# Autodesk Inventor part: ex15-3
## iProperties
Shininess: 64.0
Length Units: 11272
Angle Units: 11279
Time Units: 11290
Mass Units: 11286
Length Display Precision: 3
Angle Display Precision: 2
Compacted: True
Part Number: ex15-3
Document SubType Name: Modeling
Created: 2002-11
Designer: E. MOSS
Density: 0.0
Volumn: 0.0
Area: 0.0
PropertySet Name: Model Information
Control State: 0
Master: False
Checked Out: False
Author: E. MOSS
